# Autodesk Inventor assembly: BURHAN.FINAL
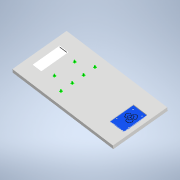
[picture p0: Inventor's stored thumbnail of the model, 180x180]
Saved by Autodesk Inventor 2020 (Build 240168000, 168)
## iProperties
Created: 2020-03
Part Number: BURHAN.FINAL
Document SubType Name: Assembly
Designer: Darugar
Author: Darugar
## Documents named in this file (5)
- C:\Users\Darugar\Desktop\Authentication part\BURHAN.FINAL.iam
- C:\Users\Darugar\Desktop\Authentication part\authi.ipt
- C:\Users\Darugar\Desktop\Ardunio\rfid.ipt
- C:\Users\Darugar\Desktop\Authentication part\bUTTON.ipt
- C:\Users\Darugar\Desktop\Authentication part\DISPL.ipt
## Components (9 placed, 4 different names)
1. authi:1 — Rigid:1, Rigid:2, Rigid:3, Rotational:1, Rotational:2, Rotational:3, Rotational:4, Rigid:4
2. rfid:1 — Rigid:1
3. bUTTON:2 — Rigid:3
4. bUTTON:3 — Rigid:2
5. bUTTON:4 — Rotational:1
6. bUTTON:5 — Rotational:3
7. bUTTON:6 — Rotational:4
8. bUTTON:7 — Rotational:2
9. DISPL:1 — Rigid:4
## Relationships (8: WeldJoint 4, RevoluteJoint 4)
- Rigid:1 [WeldJoint]: authi:1 ↔ rfid:1
- Rigid:2 [WeldJoint]: authi:1 ↔ bUTTON:3
- Rigid:3 [WeldJoint]: authi:1 ↔ bUTTON:2
- Rotational:1 [RevoluteJoint]: authi:1 ↔ bUTTON:4
- Rotational:2 [RevoluteJoint]: authi:1 ↔ bUTTON:7
- Rotational:3 [RevoluteJoint]: authi:1 ↔ bUTTON:5
- Rotational:4 [RevoluteJoint]: authi:1 ↔ bUTTON:6
- Rigid:4 [WeldJoint]: authi:1 ↔ DISPL:1
